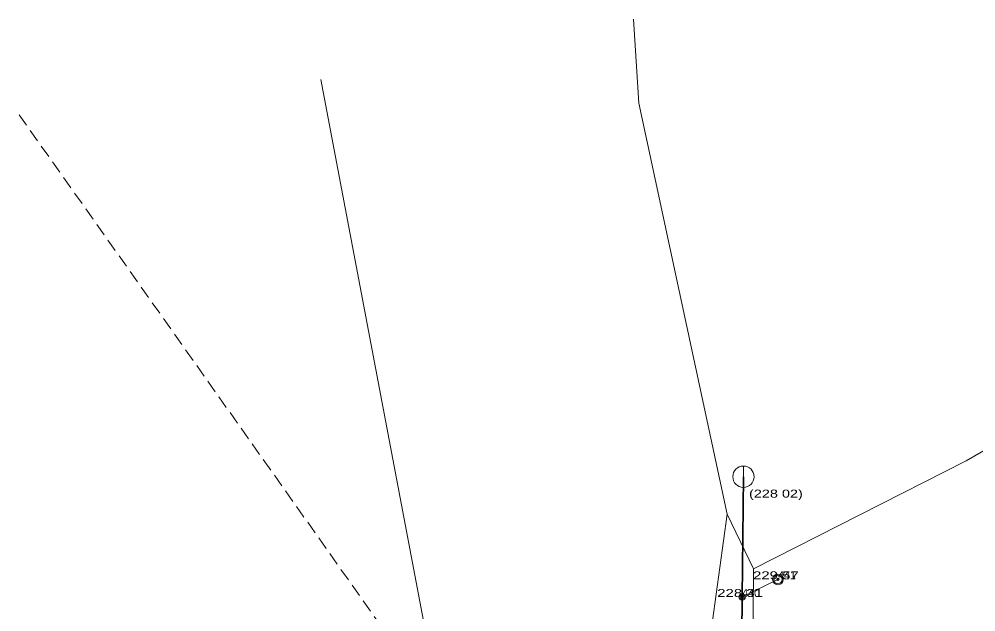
# Model space of a CAD drawing. Extents: x -686207 to -681951, y -1020493 to -1017811.
# Drawn here: x -682617.9 to -682528.3, y -1018826.8 to -1018771.2 of the extents above; entities that cross this region are included whole.
import ezdxf
from ezdxf.enums import TextEntityAlignment as Align

# ---------------------------------------------------------------- set-up
doc = ezdxf.new("R2010")
doc.units = 0
doc.header["$LTSCALE"] = 0.4
doc.header["$PDMODE"] = 32
doc.header["$PDSIZE"] = 0.2
doc.linetypes.add('LONG_DASHED', pattern=[7.5, 6, -1.5])
doc.linetypes.add('MEDIUM_DASHED', pattern=[4.5, 3, -1.5])
for name, color, linetype, lineweight in [('1', 7, 'Continuous', 13), ('10', 7, 'Continuous', 13), ('12', 7, 'Continuous', 13), ('3', 7, 'Continuous', 13), ('45', 7, 'Continuous', 35), ('50', 7, 'LONG_DASHED', 25), ('6', 7, 'Continuous', 13)]:
    doc.layers.add(name, color=color, linetype=linetype, lineweight=lineweight)
doc.layers.add('2', color=7, linetype='Continuous')

msp = doc.modelspace()

# ---------------------------------------------------------------- linework, layer by layer
at = {"layer": '1'}
for p, q in [((-682568.14, -1018890.36), (-682589.67, -1018776.87)), ((-682551.57, -1018817.6), (-682549.1, -1018822.73))]:
    msp.add_line(p, q, dxfattribs=at)
for points in [[(-682560.37, -1018771.21), (-682559.87, -1018779.09), (-682551.57, -1018817.6)], [(-682471.44, -1018784.95), (-682478.87, -1018785.32), (-682494.21, -1018784.94), (-682513.67, -1018802.25), (-682522.53, -1018808.75), (-682529.16, -1018812.61), (-682549.1, -1018822.73)], [(-682551.57, -1018817.6), (-682553.3, -1018830.1), (-682552.65, -1018840.08)], [(-682549.1, -1018822.73), (-682549.16, -1018830.55), (-682548.55, -1018839.26)]]:
    msp.add_lwpolyline(points, dxfattribs=at)
for p in [(-682546.815, -1018823.709), (-682550.17, -1018825.36)]:
    msp.add_point(p, dxfattribs=at)
at = {"layer": '10'}
msp.add_line((-682550.048, -1018813.094), (-682550.048, -1018815.842), dxfattribs=at)
msp.add_circle((-682550.048, -1018814.095), 1.0002, dxfattribs=at)
at = {"layer": '12'}
for centre, radius in [((-682546.815, -1018823.709), 0.5), ((-682546.815, -1018823.709), 0.4), ((-682550.17, -1018825.36), 0.3), ((-682550.17, -1018825.36), 0.2), ((-682550.17, -1018825.36), 0.1)]:
    msp.add_circle(centre, radius, dxfattribs=at)
at = {"layer": '45'}
for p, q in [((-682550.048, -1018814.094), (-682550.17, -1018825.36)), ((-682550.17, -1018825.36), (-682550.3, -1018837.459))]:
    msp.add_line(p, q, dxfattribs=at)
at = {"layer": '50', "linetype": 'Continuous', "lineweight": 13}
msp.add_lwpolyline([(-682550.17, -1018825.36), (-682546.815, -1018823.709), (-682550.17, -1018825.36)], dxfattribs=at)
at = {"layer": '6', "linetype": 'MEDIUM_DASHED'}
msp.add_line((-682617.94, -1018780.17), (-682575.26, -1018840.44), dxfattribs=at)

# ---------------------------------------------------------------- texts
at = {"layer": '2'}
for s, p in [('441', (-682546.81, -1018823.7)), ('440', (-682550.17, -1018825.36))]:
    msp.add_text(s, height=0.75, dxfattribs=at).set_placement(p)
at = {"layer": '3'}
for s, width, p in [('(228 02)', 1.35, (-682547.007, -1018816.049)), ('229 57 ', 1.4, (-682546.815, -1018823.709)), ('228 31 ', 1.4, (-682550.17, -1018825.36))]:
    msp.add_text(s, height=0.75, dxfattribs=dict(at, width=width)).set_placement(p, align=Align.CENTER)

doc.saveas('drawing.dxf')
